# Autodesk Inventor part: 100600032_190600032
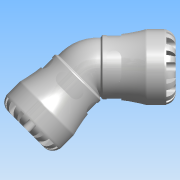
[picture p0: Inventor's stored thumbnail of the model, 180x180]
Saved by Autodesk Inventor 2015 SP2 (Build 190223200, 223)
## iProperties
Created: 2016-12
Part Number: 100600032_190600032
Material: PVC-Piping
Description: PLASSON 45° ELBOW 32-32 SERIES 1
Document SubType Name: Modeling
Designer: KIM
Mass: 664.223 g
Surface Area: 733.008 cm^2
Volume: 474.445 cm^3
Density: 1.4 g/cm^3
Appearance: Smooth - White
Author: KIM
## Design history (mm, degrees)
derived "1006.ipt"
feature "Solid1::1006.ipt"
tag "TaggingFeature1"
body "Solid1"
other parameters: "d1" = 22.68, "d2" = 32, "d4" = 58, "d8" = 49.3, "d13" = 7.2, "d14" = 7.2, "d15" = 0, "d17" = 360 deg, "d19" = 8 deg, "d20" = 0.64, "d21" = 0.64, "d22" = 8 deg, "d24" = 0, "d26" = 360 deg, "d33" = 5.8, "d43" = 45.24, "d51" = 0.58, "d54" = 11.2, "d55" = 7.04, "d57" = 14.112, "d58" = 0, "d74" = 0, "d77" = 2.66667, "d78" = 54, "d82" = 0.64, "d115" = 360 deg, "d207" = 90 deg, "d228" = 9.52, "d247" = 1.16, "d248" = 3.24, "d268" = 10.353, "d269" = 3.1059, "d270" = 67, "d277" = 135 deg, "d279" = 3.1059, "d280" = 135 deg, "d281" = 0, "d282" = 0, "d_" = 32, "E_" = 58, "l_" = 54, "A_" = 67, "d9" = 9, "d11" = 58
